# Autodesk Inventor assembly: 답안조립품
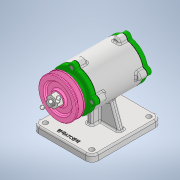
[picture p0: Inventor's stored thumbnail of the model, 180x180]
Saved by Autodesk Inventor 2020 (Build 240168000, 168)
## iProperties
Created: 2022-11
Part Number: 답안조립품
Document SubType Name: Assembly
Designer: Owner
Author: Owner
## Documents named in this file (12)
- C:\Users\Owner\Desktop\721108V1009\답안조립품.iam
- C:\Users\Owner\Desktop\721108V1009\본체.ipt
- C:\Users\Owner\Desktop\721108V1009\V-벨트풀리.ipt
- C:\Users\Owner\Desktop\721108V1009\개스킷.ipt
- C:\Users\Owner\Desktop\721108V1009\너트 M12 x 1.25.ipt
- C:\Users\Owner\Desktop\721108V1009\뒤커버.ipt
- C:\Users\Owner\Desktop\721108V1009\베어링 6204.ipt
- C:\Users\Owner\Desktop\721108V1009\볼트 M4 x 12.ipt
- C:\Users\Owner\Desktop\721108V1009\앞커버.ipt
- C:\Users\Owner\Desktop\721108V1009\오일 실.ipt
- C:\Users\Owner\Desktop\721108V1009\축.ipt
- C:\Users\Owner\Desktop\721108V1009\키 4 x 4.ipt
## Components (8 placed, 6 different names)
1. V-벨트풀리:1
2. 개스킷:1
3. KS B 1012 클래스 1 일반 - 미터 M12x1.25:1 — 각도:1
4. KS B 2023 6204 - 20 x 47 x 14:1
5. KS B 2804 D D - 20 32 8:1
6. KS B 1311 (I) 4 x 4 x 12:1
7. KS B 2023 6204 - 20 x 47 x 14:2
8. 개스킷:2
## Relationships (1: Angle 1)
- 각도:1 [Angle]: KS B 1012 클래스 1 일반 - 미터 M12x1.25:1
